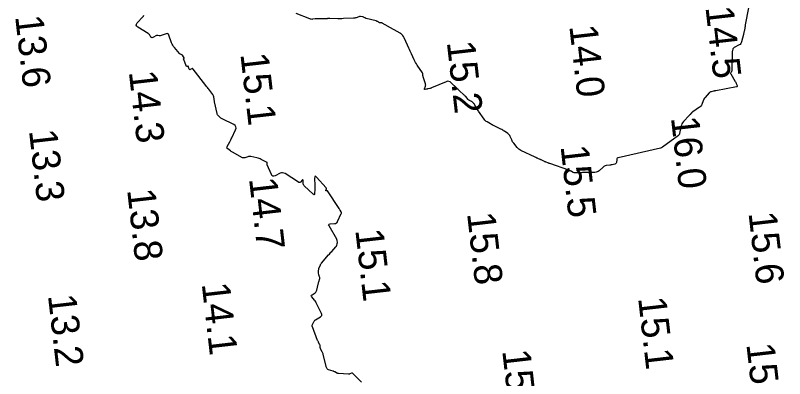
# Model space of a CAD drawing. Extents: x 1023796 to 1112670, y 656573 to 837340.
# Drawn here: x 1109782.9 to 1109919.9, y 681189.4 to 681254.1 of the extents above; entities that cross this region are included whole.
import ezdxf

# ---------------------------------------------------------------- set-up
doc = ezdxf.new("R2010")
doc.units = 0
doc.layers.add('V-CHAN-CONT-15FT', color=7, linetype='Continuous')
doc.layers.add('V-TOPO-SOUN', color=7, linetype='Continuous')

msp = doc.modelspace()

# ---------------------------------------------------------------- linework, layer by layer
at = {"layer": 'V-CHAN-CONT-15FT'}
for points in [[(1109913.48, 681255.39), (1109912.93, 681252.37), (1109912.9, 681252.23), (1109912.88, 681252.08), (1109912.85, 681251.94), (1109912.83, 681251.79), (1109912.72, 681251.21), (1109912.69, 681251.07), (1109912.66, 681250.93), (1109912.63, 681250.78), (1109912.6, 681250.64), (1109912.28, 681249.38), (1109912.21, 681249.2), (1109912.12, 681249.04), (1109911.99, 681248.91), (1109911.83, 681248.81), (1109910.94, 681248.34), (1109910.87, 681248.3), (1109910.81, 681248.24), (1109910.76, 681248.17), (1109910.73, 681248.09), (1109910.64, 681247.75), (1109910.62, 681247.66), (1109910.6, 681247.58), (1109910.59, 681247.49), (1109910.59, 681247.4), (1109910.53, 681244.24), (1109910.53, 681244.19), (1109910.52, 681244.14), (1109910.5, 681244.09), (1109910.47, 681244.05), (1109910.35, 681243.87), (1109910.33, 681243.83), (1109910.32, 681243.78), (1109910.32, 681243.74), (1109910.34, 681243.69), (1109911.15, 681242.31), (1109911.2, 681242.22), (1109911.25, 681242.13), (1109911.29, 681242.04), (1109911.33, 681241.94), (1109911.49, 681241.56), (1109911.51, 681241.48), (1109911.5, 681241.41), (1109911.45, 681241.36), (1109911.37, 681241.34), (1109907.67, 681240.65), (1109907.57, 681240.63), (1109907.47, 681240.61), (1109907.36, 681240.59), (1109907.26, 681240.57), (1109906.85, 681240.48), (1109906.75, 681240.46), (1109906.66, 681240.41), (1109906.57, 681240.36), (1109906.5, 681240.28), (1109905.78, 681239.46), (1109905.67, 681239.32), (1109905.57, 681239.18), (1109905.49, 681239.03), (1109905.42, 681238.87), (1109905.17, 681238.23), (1109905.1, 681238.07), (1109905.01, 681237.93), (1109904.89, 681237.81), (1109904.76, 681237.71), (1109903.56, 681236.9), (1109903.54, 681236.88), (1109903.52, 681236.86), (1109903.5, 681236.84), (1109903.47, 681236.82), (1109903.39, 681236.74), (1109903.37, 681236.72), (1109903.35, 681236.7), (1109903.33, 681236.68), (1109903.31, 681236.66), (1109903.09, 681236.44), (1109903.05, 681236.39), (1109903.01, 681236.35), (1109902.96, 681236.3), (1109902.92, 681236.26), (1109901.91, 681235.15), (1109901.75, 681234.96), (1109901.63, 681234.75), (1109901.54, 681234.53), (1109901.47, 681234.29), (1109901.23, 681233.01), (1109901.2, 681232.92), (1109901.16, 681232.83), (1109901.1, 681232.75), (1109901.03, 681232.69), (1109900.71, 681232.43), (1109900.63, 681232.37), (1109900.54, 681232.31), (1109900.46, 681232.25), (1109900.38, 681232.19), (1109898.15, 681230.6), (1109898.15, 681230.59), (1109898.14, 681230.58), (1109898.13, 681230.58), (1109898.13, 681230.57), (1109898.1, 681230.55), (1109898.09, 681230.54), (1109898.08, 681230.54), (1109898.08, 681230.53), (1109898.07, 681230.53), (1109897.91, 681230.46), (1109897.89, 681230.45), (1109897.86, 681230.44), (1109897.83, 681230.43), (1109897.8, 681230.43), (1109890.3, 681228.73), (1109890.19, 681228.69), (1109890.1, 681228.62), (1109890.05, 681228.53), (1109890.02, 681228.41), (1109889.95, 681227.86), (1109889.92, 681227.76), (1109889.87, 681227.68), (1109889.79, 681227.62), (1109889.69, 681227.58), (1109889.23, 681227.48), (1109889.12, 681227.45), (1109889, 681227.43), (1109888.89, 681227.41), (1109888.77, 681227.39), (1109888.12, 681227.31), (1109887.98, 681227.28), (1109887.85, 681227.23), (1109887.72, 681227.16), (1109887.61, 681227.07), (1109886.87, 681226.4), (1109886.71, 681226.28), (1109886.53, 681226.19), (1109886.34, 681226.13), (1109886.13, 681226.11), (1109884.27, 681226.08), (1109884.09, 681226.08), (1109883.92, 681226.07), (1109883.74, 681226.06), (1109883.57, 681226.06), (1109882.61, 681226.01), (1109882.57, 681226.01), (1109882.53, 681226.01), (1109882.49, 681226.02), (1109882.45, 681226.04), (1109882.29, 681226.1), (1109882.25, 681226.12), (1109882.21, 681226.14), (1109882.17, 681226.16), (1109882.14, 681226.17), (1109881.9, 681226.3), (1109881.86, 681226.32), (1109881.83, 681226.34), (1109881.79, 681226.36), (1109881.76, 681226.38), (1109881.63, 681226.46), (1109881.59, 681226.48), (1109881.56, 681226.5), (1109881.52, 681226.52), (1109881.48, 681226.53), (1109878.08, 681227.68), (1109878, 681227.7), (1109877.92, 681227.73), (1109877.85, 681227.76), (1109877.77, 681227.8), (1109877.46, 681227.92), (1109877.39, 681227.96), (1109877.31, 681227.99), (1109877.23, 681228.02), (1109877.16, 681228.06), (1109876.66, 681228.28), (1109876.58, 681228.32), (1109876.5, 681228.35), (1109876.43, 681228.39), (1109876.35, 681228.42), (1109875.96, 681228.6), (1109875.92, 681228.61), (1109875.89, 681228.63), (1109875.85, 681228.65), (1109875.81, 681228.67), (1109875.66, 681228.74), (1109875.59, 681228.77), (1109875.51, 681228.81), (1109872.95, 681230.02), (1109872.76, 681230.13), (1109872.59, 681230.25), (1109872.43, 681230.39), (1109872.28, 681230.55), (1109871.67, 681231.29), (1109871.57, 681231.43), (1109871.47, 681231.57), (1109871.39, 681231.72), (1109871.32, 681231.88), (1109871.05, 681232.53), (1109870.98, 681232.69), (1109870.88, 681232.82), (1109870.76, 681232.94), (1109870.63, 681233.05), (1109870.01, 681233.45), (1109869.85, 681233.54), (1109869.7, 681233.63), (1109869.54, 681233.72), (1109869.38, 681233.8), (1109868.16, 681234.41), (1109868, 681234.49), (1109867.84, 681234.57), (1109867.69, 681234.66), (1109867.53, 681234.74), (1109866.91, 681235.09), (1109866.76, 681235.19), (1109866.63, 681235.3), (1109866.51, 681235.42), (1109866.4, 681235.56), (1109865.41, 681237.02), (1109865.32, 681237.15), (1109865.23, 681237.29), (1109865.14, 681237.42), (1109865.05, 681237.56), (1109864.59, 681238.3), (1109864.56, 681238.34), (1109864.53, 681238.39), (1109864.5, 681238.43), (1109864.46, 681238.47), (1109864.3, 681238.63), (1109864.27, 681238.66), (1109864.22, 681238.7), (1109864.18, 681238.73), (1109864.13, 681238.75), (1109863.8, 681238.91), (1109863.74, 681238.95), (1109863.67, 681238.99), (1109863.61, 681239.04), (1109863.56, 681239.1), (1109863.12, 681239.6), (1109863.03, 681239.7), (1109862.93, 681239.8), (1109862.84, 681239.89), (1109862.73, 681239.99), (1109862.04, 681240.6), (1109861.89, 681240.73), (1109861.74, 681240.87), (1109861.6, 681241.01), (1109861.45, 681241.15), (1109860.54, 681242.08), (1109860.34, 681242.24), (1109860.11, 681242.32), (1109859.88, 681242.33), (1109859.62, 681242.26), (1109857.01, 681241.14), (1109856.94, 681241.11), (1109856.87, 681241.09), (1109856.8, 681241.07), (1109856.73, 681241.05), (1109856.43, 681241.01), (1109856.36, 681240.99), (1109856.29, 681240.98), (1109856.22, 681240.96), (1109856.15, 681240.95), (1109855.87, 681240.87), (1109855.82, 681240.87), (1109855.78, 681240.88), (1109855.77, 681240.92), (1109855.78, 681240.97), (1109855.94, 681241.46), (1109855.97, 681241.56), (1109855.98, 681241.67), (1109855.97, 681241.77), (1109855.95, 681241.87), (1109855.53, 681243.11), (1109855.51, 681243.17), (1109855.5, 681243.23), (1109855.49, 681243.3), (1109855.48, 681243.36), (1109855.48, 681243.61), (1109855.47, 681243.67), (1109855.46, 681243.73), (1109855.44, 681243.78), (1109855.41, 681243.83), (1109854.47, 681245.2), (1109854.32, 681245.43), (1109854.17, 681245.68), (1109854.04, 681245.92), (1109853.91, 681246.18), (1109853.43, 681247.21), (1109853.31, 681247.46), (1109853.19, 681247.72), (1109853.07, 681247.98), (1109852.95, 681248.24), (1109852.2, 681249.95), (1109852.17, 681249.99), (1109852.15, 681250.04), (1109852.13, 681250.08), (1109852.1, 681250.13), (1109852, 681250.3), (1109851.98, 681250.34), (1109851.95, 681250.38), (1109851.92, 681250.42), (1109851.89, 681250.46), (1109851.67, 681250.72), (1109851.62, 681250.77), (1109851.56, 681250.82), (1109851.5, 681250.86), (1109851.44, 681250.9), (1109849.18, 681252.16), (1109849.07, 681252.22), (1109848.97, 681252.27), (1109848.87, 681252.33), (1109848.77, 681252.39), (1109848.25, 681252.7), (1109848.21, 681252.72), (1109848.17, 681252.74), (1109848.13, 681252.74), (1109848.09, 681252.74), (1109847.91, 681252.73), (1109847.87, 681252.73), (1109847.83, 681252.74), (1109847.79, 681252.75), (1109847.75, 681252.77), (1109847.42, 681252.96), (1109847.36, 681253), (1109847.29, 681253.03), (1109847.21, 681253.06), (1109847.14, 681253.08), (1109845.37, 681253.54), (1109845.31, 681253.56), (1109845.25, 681253.58), (1109845.19, 681253.61), (1109845.14, 681253.64), (1109844.92, 681253.76), (1109844.86, 681253.79), (1109844.81, 681253.81), (1109844.75, 681253.83), (1109844.69, 681253.84), (1109844.37, 681253.87), (1109844.3, 681253.87), (1109844.23, 681253.87), (1109844.16, 681253.85), (1109844.09, 681253.83), (1109843.58, 681253.66), (1109843.47, 681253.62), (1109843.36, 681253.6), (1109843.25, 681253.58), (1109843.14, 681253.57), (1109841.31, 681253.49), (1109841.06, 681253.48), (1109840.81, 681253.47), (1109840.56, 681253.47), (1109840.31, 681253.48), (1109838.91, 681253.51), (1109838.86, 681253.51), (1109838.81, 681253.51), (1109838.76, 681253.51), (1109838.71, 681253.5), (1109838.5, 681253.49), (1109838.45, 681253.48), (1109838.39, 681253.48), (1109838.34, 681253.48), (1109838.29, 681253.48), (1109836.8, 681253.48), (1109836.67, 681253.48), (1109836.55, 681253.47), (1109836.42, 681253.46), (1109836.3, 681253.45), (1109835.79, 681253.37), (1109835.67, 681253.36), (1109835.55, 681253.37), (1109835.43, 681253.39), (1109835.31, 681253.43), (1109832.9, 681254.43)], [(1109844.54, 681188.74), (1109842.99, 681190.29), (1109842.94, 681190.33), (1109842.88, 681190.35), (1109842.82, 681190.35), (1109842.76, 681190.33), (1109842.49, 681190.21), (1109842.43, 681190.19), (1109842.36, 681190.17), (1109842.29, 681190.16), (1109842.21, 681190.16), (1109840.42, 681190.3), (1109840.34, 681190.31), (1109840.25, 681190.33), (1109840.17, 681190.36), (1109840.09, 681190.4), (1109839.79, 681190.58), (1109839.71, 681190.62), (1109839.63, 681190.66), (1109839.55, 681190.69), (1109839.47, 681190.72), (1109838.68, 681190.96), (1109838.54, 681191.03), (1109838.43, 681191.12), (1109838.34, 681191.24), (1109838.29, 681191.39), (1109837.72, 681193.69), (1109837.69, 681193.81), (1109837.65, 681193.92), (1109837.6, 681194.03), (1109837.55, 681194.14), (1109837.26, 681194.67), (1109837.24, 681194.73), (1109837.22, 681194.79), (1109837.2, 681194.85), (1109837.2, 681194.92), (1109837.2, 681195.18), (1109837.19, 681195.25), (1109837.18, 681195.31), (1109837.16, 681195.37), (1109837.13, 681195.43), (1109836.9, 681195.84), (1109836.85, 681195.93), (1109836.81, 681196.02), (1109836.76, 681196.11), (1109836.73, 681196.2), (1109835.79, 681198.58), (1109835.75, 681198.69), (1109835.74, 681198.81), (1109835.76, 681198.92), (1109835.8, 681199.04), (1109836.03, 681199.49), (1109836.09, 681199.6), (1109836.16, 681199.7), (1109836.25, 681199.78), (1109836.35, 681199.85), (1109837.22, 681200.38), (1109837.37, 681200.5), (1109837.45, 681200.64), (1109837.46, 681200.8), (1109837.4, 681200.98), (1109836.55, 681202.76), (1109836.47, 681202.91), (1109836.38, 681203.06), (1109836.28, 681203.21), (1109836.17, 681203.35), (1109835.68, 681203.92), (1109835.61, 681204.03), (1109835.6, 681204.14), (1109835.64, 681204.24), (1109835.74, 681204.33), (1109836.27, 681204.67), (1109836.39, 681204.76), (1109836.48, 681204.88), (1109836.55, 681205), (1109836.6, 681205.15), (1109836.81, 681206.18), (1109836.84, 681206.29), (1109836.87, 681206.41), (1109836.9, 681206.53), (1109836.93, 681206.64), (1109837.12, 681207.23), (1109837.13, 681207.28), (1109837.14, 681207.33), (1109837.13, 681207.38), (1109837.11, 681207.42), (1109837.02, 681207.61), (1109837, 681207.65), (1109836.98, 681207.7), (1109836.97, 681207.75), (1109836.96, 681207.8), (1109836.88, 681208.3), (1109836.87, 681208.37), (1109836.87, 681208.45), (1109836.87, 681208.52), (1109836.88, 681208.6), (1109836.92, 681208.9), (1109836.93, 681208.98), (1109836.95, 681209.05), (1109836.98, 681209.12), (1109837.01, 681209.19), (1109837.21, 681209.61), (1109837.26, 681209.71), (1109837.32, 681209.79), (1109837.38, 681209.88), (1109837.44, 681209.96), (1109838.67, 681211.41), (1109838.81, 681211.57), (1109838.95, 681211.73), (1109839.09, 681211.88), (1109839.23, 681212.04), (1109839.98, 681212.86), (1109840.02, 681212.92), (1109840.06, 681212.98), (1109840.09, 681213.05), (1109840.12, 681213.12), (1109840.21, 681213.42), (1109840.23, 681213.49), (1109840.24, 681213.55), (1109840.24, 681213.61), (1109840.24, 681213.68), (1109840.22, 681213.94), (1109840.21, 681214.01), (1109840.2, 681214.07), (1109840.17, 681214.13), (1109840.14, 681214.19), (1109838.76, 681216.58), (1109838.69, 681216.73), (1109838.71, 681216.84), (1109838.79, 681216.91), (1109838.95, 681216.94), (1109839.73, 681216.99), (1109839.91, 681217.02), (1109840.06, 681217.1), (1109840.19, 681217.21), (1109840.28, 681217.37), (1109840.93, 681218.79), (1109840.95, 681218.87), (1109840.96, 681218.94), (1109840.94, 681219.02), (1109840.91, 681219.1), (1109840.72, 681219.4), (1109840.68, 681219.47), (1109840.63, 681219.55), (1109840.58, 681219.62), (1109840.54, 681219.7), (1109838.51, 681222.8), (1109838.49, 681222.82), (1109838.46, 681222.84), (1109838.44, 681222.85), (1109838.4, 681222.85), (1109838.26, 681222.83), (1109838.23, 681222.83), (1109838.21, 681222.83), (1109838.21, 681222.85), (1109838.21, 681222.88), (1109838.28, 681223.17), (1109838.29, 681223.23), (1109838.28, 681223.28), (1109838.26, 681223.33), (1109838.23, 681223.38), (1109836.55, 681225.25), (1109836.39, 681225.4), (1109836.28, 681225.43), (1109836.21, 681225.33), (1109836.19, 681225.11), (1109836.23, 681223.78), (1109836.23, 681223.6), (1109836.23, 681223.42), (1109836.23, 681223.24), (1109836.22, 681223.06), (1109836.18, 681222.35), (1109836.16, 681222.2), (1109836.1, 681222.14), (1109836.02, 681222.15), (1109835.91, 681222.23), (1109834.33, 681223.74), (1109834.25, 681223.83), (1109834.19, 681223.93), (1109834.16, 681224.04), (1109834.14, 681224.15), (1109834.13, 681224.66), (1109834.12, 681224.75), (1109834.08, 681224.79), (1109834.03, 681224.78), (1109833.96, 681224.72), (1109833.65, 681224.39), (1109833.57, 681224.32), (1109833.48, 681224.29), (1109833.39, 681224.3), (1109833.29, 681224.35), (1109830.92, 681225.89), (1109830.71, 681226), (1109830.49, 681226.04), (1109830.27, 681226.02), (1109830.04, 681225.95), (1109829.13, 681225.51), (1109828.92, 681225.44), (1109828.74, 681225.46), (1109828.59, 681225.56), (1109828.48, 681225.75), (1109827.73, 681227.46), (1109827.72, 681227.5), (1109827.72, 681227.53), (1109827.72, 681227.56), (1109827.72, 681227.6), (1109827.76, 681227.74), (1109827.77, 681227.77), (1109827.76, 681227.8), (1109827.75, 681227.83), (1109827.72, 681227.85), (1109826.69, 681228.42), (1109826.5, 681228.51), (1109826.31, 681228.59), (1109826.11, 681228.66), (1109825.91, 681228.71), (1109824.8, 681228.93), (1109824.67, 681228.95), (1109824.53, 681228.95), (1109824.4, 681228.94), (1109824.26, 681228.9), (1109823.73, 681228.73), (1109823.59, 681228.7), (1109823.46, 681228.7), (1109823.34, 681228.72), (1109823.21, 681228.78), (1109821.7, 681229.63), (1109821.58, 681229.7), (1109821.45, 681229.78), (1109821.33, 681229.86), (1109821.2, 681229.95), (1109820.72, 681230.29), (1109820.62, 681230.38), (1109820.58, 681230.48), (1109820.57, 681230.6), (1109820.62, 681230.72), (1109821.05, 681231.53), (1109821.15, 681231.7), (1109821.24, 681231.88), (1109821.33, 681232.06), (1109821.42, 681232.25), (1109822.1, 681233.71), (1109822.19, 681233.99), (1109822.17, 681234.24), (1109822.03, 681234.45), (1109821.78, 681234.61), (1109819.69, 681235.64), (1109819.59, 681235.69), (1109819.5, 681235.75), (1109819.41, 681235.82), (1109819.33, 681235.9), (1109819.01, 681236.22), (1109818.94, 681236.3), (1109818.88, 681236.39), (1109818.83, 681236.49), (1109818.8, 681236.6), (1109818.36, 681238.68), (1109818.34, 681238.77), (1109818.32, 681238.87), (1109818.3, 681238.97), (1109818.29, 681239.07), (1109818.21, 681239.6), (1109818.2, 681239.63), (1109818.19, 681239.66), (1109818.18, 681239.7), (1109818.17, 681239.73), (1109818.11, 681239.86), (1109818.09, 681239.89), (1109818.08, 681239.92), (1109818.06, 681239.95), (1109818.04, 681239.98), (1109817.32, 681240.91), (1109817.19, 681241.08), (1109817.07, 681241.24), (1109816.94, 681241.41), (1109816.81, 681241.57), (1109814.55, 681244.52), (1109814.5, 681244.57), (1109814.44, 681244.6), (1109814.38, 681244.6), (1109814.31, 681244.58), (1109814.03, 681244.43), (1109813.97, 681244.4), (1109813.91, 681244.41), (1109813.87, 681244.44), (1109813.84, 681244.5), (1109813.64, 681245), (1109813.63, 681245.02), (1109813.61, 681245.04), (1109813.59, 681245.04), (1109813.57, 681245.03), (1109813.46, 681244.96), (1109813.43, 681244.95), (1109813.41, 681244.95), (1109813.39, 681244.97), (1109813.38, 681244.99), (1109812.84, 681246.31), (1109812.83, 681246.33), (1109812.83, 681246.35), (1109812.84, 681246.36), (1109812.86, 681246.38), (1109812.94, 681246.42), (1109812.96, 681246.43), (1109812.97, 681246.45), (1109812.97, 681246.47), (1109812.96, 681246.49), (1109812.72, 681246.88), (1109812.69, 681246.93), (1109812.64, 681246.97), (1109812.59, 681247.01), (1109812.54, 681247.04), (1109812.3, 681247.14), (1109812.25, 681247.17), (1109812.19, 681247.2), (1109812.14, 681247.24), (1109812.1, 681247.29), (1109811.19, 681248.34), (1109811.03, 681248.53), (1109810.9, 681248.74), (1109810.78, 681248.96), (1109810.69, 681249.2), (1109810.23, 681250.56), (1109810.15, 681250.72), (1109810.03, 681250.81), (1109809.89, 681250.84), (1109809.72, 681250.8), (1109808.69, 681250.43), (1109808.64, 681250.42), (1109808.58, 681250.41), (1109808.52, 681250.41), (1109808.47, 681250.42), (1109808.24, 681250.49), (1109808.19, 681250.5), (1109808.13, 681250.5), (1109808.08, 681250.49), (1109808.02, 681250.47), (1109807.33, 681250.13), (1109807.24, 681250.1), (1109807.16, 681250.11), (1109807.09, 681250.14), (1109807.03, 681250.22), (1109806.8, 681250.57), (1109806.74, 681250.66), (1109806.67, 681250.74), (1109806.59, 681250.8), (1109806.51, 681250.86), (1109804.7, 681251.96), (1109804.49, 681252.13), (1109804.4, 681252.32), (1109804.44, 681252.52), (1109804.59, 681252.74), (1109805.59, 681253.8), (1109805.7, 681253.95), (1109805.76, 681254.12)]]:
    msp.add_lwpolyline(points, dxfattribs=at)

# ---------------------------------------------------------------- texts
at = {"layer": 'V-TOPO-SOUN'}
for s, p in [('14.5 ', (1109905.82, 681255.52)), ('13.6 ', (1109782.81, 681253.89)), ('14.0 ', (1109881.56, 681252.17)), ('15.2 ', (1109859.73, 681249.31)), ('15.1 ', (1109822.95, 681247.18)), ('14.3 ', (1109803.07, 681244.03)), ('16.0 ', (1109899.67, 681235.86)), ('13.3 ', (1109785.28, 681233.56)), ('15.5 ', (1109880, 681230.75)), ('14.7 ', (1109824.49, 681225)), ('13.8 ', (1109802.77, 681223)), ('15.8 ', (1109863.34, 681218.8)), ('15.6 ', (1109913.49, 681218.89)), ('15.1 ', (1109843.43, 681215.85)), ('14.1 ', (1109816.06, 681206.27)), ('13.2 ', (1109788.66, 681204.2)), ('15.1 ', (1109893.82, 681203.74)), ('15.8 ', (1109913.11, 681195.51)), ('15.1 ', (1109869.61, 681194.36))]:
    msp.add_text(s, height=5, rotation=276.5594, dxfattribs=at).set_placement(p)

doc.saveas('drawing.dxf')
